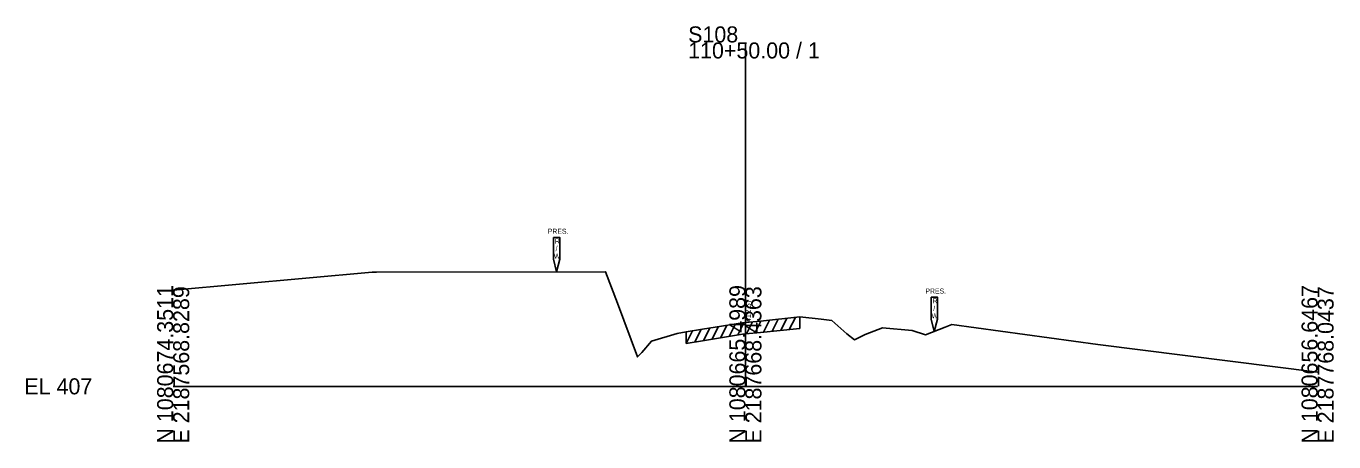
# Model space of a CAD drawing. Extents: x -26 to 2203, y 490 to 19581.
# Drawn here: x -25.7 to 202.8, y 14490.3 to 14562.9 of the extents above; entities that cross this region are included whole.
import ezdxf

# ---------------------------------------------------------------- set-up
doc = ezdxf.new("R2010")
doc.units = 0
for name, color, linetype in [('RD_GPK_XS_Cell', 7, 'Continuous'), ('RD_XS_ExGround', 7, 'Continuous'), ('RD_XS_ExPaveRet', 7, 'Continuous'), ('RD_XS_ExRW', 7, 'Continuous'), ('RD_XS_TX_Elev_EX', 7, 'Continuous')]:
    doc.layers.add(name, color=color, linetype=linetype)

msp = doc.modelspace()

# ---------------------------------------------------------------- linework, layer by layer
at = {"layer": 'RD_GPK_XS_Cell'}
for p, q in [((100, 14500), (100, 14560.07)), ((0, 14500), (100, 14500)), ((100, 14500), (200, 14500))]:
    msp.add_line(p, q, dxfattribs=at)
at = {"layer": 'RD_XS_ExGround'}
msp.add_lwpolyline([(0, 14516.79), (34.79, 14519.96), (35.53, 14519.96), (75.57, 14520.02), (77.63, 14514.53), (81.15, 14505.14), (81.89, 14505.91), (83.57, 14507.91), (88.06, 14509.21), (89.67, 14509.51), (92.5, 14509.96), (99.49, 14511.1), (100, 14511.15), (102.65, 14511.4), (109.5, 14512.12), (113.22, 14511.73), (115.08, 14511.49), (117.74, 14509.17), (119.08, 14508.13), (120.94, 14509.06), (123.98, 14510.22), (129.12, 14509.73), (131.5, 14508.97), (134.9, 14510.33), (136.08, 14510.8), (161.62, 14507.28), (200, 14502.46)], dxfattribs=at)
at = {"layer": 'RD_XS_ExPaveRet'}
for p, q in [((106.17, 14509.77), (107.23, 14511.88)), ((107.67, 14509.93), (108.73, 14512.04)), ((109.5, 14512.12), (109.5, 14510.12)), ((89.67, 14507.51), (90.76, 14509.68)), ((91.17, 14507.75), (92.26, 14509.92)), ((92.67, 14507.99), (93.76, 14510.17)), ((94.17, 14508.23), (95.26, 14510.41)), ((95.67, 14508.48), (96.76, 14510.65)), ((97.17, 14508.72), (98.26, 14510.9)), ((98.67, 14508.97), (99.75, 14511.12)), ((100.17, 14509.17), (101.22, 14511.27)), ((101.67, 14509.31), (102.72, 14511.41)), ((102.65, 14509.4), (109.5, 14510.12)), ((103.17, 14509.46), (104.23, 14511.57)), ((104.67, 14509.61), (105.73, 14511.72)), ((89.67, 14507.51), (89.67, 14509.51)), ((89.67, 14507.51), (92.5, 14507.96)), ((92.5, 14507.96), (99.49, 14509.1)), ((99.49, 14509.1), (100, 14509.15)), ((100, 14509.15), (102.65, 14509.4))]:
    msp.add_line(p, q, dxfattribs=at)
at = {"layer": 'RD_XS_ExRW'}
for points in [[(66.45, 14526.02), (67.55, 14526.02), (67.55, 14522.2), (67, 14520.01), (66.45, 14522.2)], [(132.45, 14515.59), (133.55, 14515.59), (133.55, 14511.76), (133, 14509.57), (132.45, 14511.76)]]:
    msp.add_lwpolyline(points, close=True, dxfattribs=at)

# ---------------------------------------------------------------- texts
at = {"layer": 'RD_GPK_XS_Cell'}
for s, p in [('S108', (90, 14560.07)), ('110+50.00 / 1', (90, 14557.27)), ('EL 407', (-26, 14498.6))]:
    msp.add_text(s, height=2.8, dxfattribs=at).set_placement(p)
for s, p in [('N 1080674.3511', (0, 14490)), ('E 2187568.8289', (2.8, 14490)), ('N 1080665.4989', (100, 14490)), ('E 2187668.4363', (102.8, 14490)), ('N 1080656.6467', (200, 14490)), ('E 2187768.0437', (202.8, 14490))]:
    msp.add_text(s, height=2.8, rotation=90, dxfattribs=at).set_placement(p)
at = {"layer": 'RD_XS_ExRW'}
for s, p in [('PRES.', (65.45, 14526.65)), ('R', (66.71, 14524.93)), ('/', (66.83, 14523.62)), ('W', (66.53, 14522.31)), ('PRES.', (131.45, 14516.21)), ('R', (132.71, 14514.49)), ('W', (132.53, 14511.87)), ('/', (132.83, 14513.18))]:
    msp.add_text(s, height=0.875, dxfattribs=at).set_placement(p)
at = {"layer": 'RD_XS_TX_Elev_EX'}
msp.add_text('412.57', height=1, rotation=90, dxfattribs=at).set_placement((101, 14511.15))

doc.saveas('drawing.dxf')
